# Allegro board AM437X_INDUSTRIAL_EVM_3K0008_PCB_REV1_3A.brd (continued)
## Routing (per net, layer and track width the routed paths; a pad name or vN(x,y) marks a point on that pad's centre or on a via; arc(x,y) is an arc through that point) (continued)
DDR_D30: length 36.7
  TOP w0.102: U11.AC1 87.81,58.53 88.35,58.53 88.9,59.08 91.89,59.08 92.99,57.98 92.99,55.91 94.93,53.97 94.93,52.95 95.05,52.83 95.05,52.62 96.17,51.5 97.74,51.5 98.25,51 98.25,49.47 98.04,49.26 97.31,49.26 97.19,49.14 97.19,48.98 97.31,48.86 98.13,48.86 98.25,48.74 98.25,48.57 98.13,48.45 97.2,48.45 97.08,48.33 97.08,48.16 97.2,48.04 98.13,48.04 98.25,47.92 98.25,46.07 98.13,45.95 97.88,45.95 97.76,45.83 97.76,45.66 97.88,45.54 98.13,45.54 98.25,45.43 98.25,45.26 98.13,45.14 97.88,45.14 97.76,45.02 97.76,44.85 97.88,44.73 98.13,44.73 98.25,44.61 98.25,44.33 97.4,43.49 v1(96.63,43.49) ; U21.B8 94.5,39.84 94.5,39.85 94.36,39.99 94.36,40.8 95.25,41.68 96.28,41.68 96.6,42 v1(96.6,42.24)
  BOTTOM w0.102: v1(96.6,42.24) 96.38,42.47 96.38,43.23 v1(96.63,43.49)
DDR_D31: length 36.8
  TOP w0.102: v1(95.57,53.11) 95.97,53.11 96.3,53.44 96.3,54.23 96.15,54.38 95.28,54.38 95.07,54.6 95.07,54.77 95.45,55.15 95.45,55.32 95.33,55.44 95.17,55.44 94.78,55.05 94.61,55.05 94.49,55.17 94.49,55.34 94.88,55.73 94.88,55.9 94.76,56.02 94.59,56.02 94.2,55.63 94.03,55.63 93.48,56.18 93.48,58.56 92.39,59.66 87.33,59.66 U11.AC2 ; v1(91.74,51) 91.74,50.4 90.55,49.21 90.55,40.59 U21.A3
  BOTTOM w0.102: v1(95.57,53.11) 95.56,53.1 95.56,51.93 95.87,51.61 95.87,51.45 95.76,51.33 95.6,51.33 95.06,51.87 94.9,51.87 94.78,51.76 94.78,51.59 95.32,51.06 95.32,50.9 95.21,50.78 95.04,50.78 94.51,51.32 94.35,51.32 94.03,51 v1(91.74,51)
DDR_DQM0: length 37.7
  TOP w0.102: U11.F4 v1(75.61,61.69) ; U20.E7 75.26,37.46 74.95,37.78 74.8,37.78 74.71,37.68 74.71,37.38 74.57,37.25 74.27,37.25 74.13,37.1 73.96,37.1 73.85,37.21 73.85,37.38 74.37,37.9 74.37,38.02 74.06,38.33 v1(73.63,38.33)
  BOTTOM w0.102: v1(73.63,38.33) 73.15,38.81 73.15,40.61 72.6,41.16 72.6,42.71 71.74,43.57 70.67,43.57 70.16,43.57 69.7,44.03 69.7,45.16 69.04,45.82 69.04,52.83 70.08,53.87 71.9,53.87 73.1,55.07 73.27,55.07 73.39,54.95 73.56,54.95 73.68,55.07 73.68,55.24 73.55,55.36 73.55,55.53 73.67,55.65 73.84,55.65 73.96,55.53 74.13,55.53 74.25,55.65 74.25,55.81 74.13,55.94 74.13,56.11 74.25,56.22 74.42,56.22 74.54,56.1 74.71,56.1 74.83,56.22 74.83,56.39 74.7,56.51 74.7,56.8 74.92,57.02 75.02,57.02 75.14,57.14 75.14,57.3 75.02,57.42 74.92,57.42 74.8,57.54 74.8,57.71 74.92,57.83 75.02,57.83 75.14,57.95 75.14,58.12 75.02,58.24 74.92,58.24 74.8,58.35 74.8,58.52 74.92,58.64 75.02,58.64 75.14,58.76 75.14,58.93 75.02,59.05 74.92,59.05 74.8,59.17 74.8,59.46 75.9,60.55 75.9,61.4 v1(75.61,61.69)
DDR_DQM1: length 31.7
  TOP w0.102: U20.D3 72.24,38.2 72.24,38.53 72.39,38.68 72.39,38.73 73.33,39.68 73.33,41.35 71.06,43.62 v1(71.06,44.8) ; v1(71.06,46.17) 71.06,46.53 71.32,46.78 71.48,46.78 71.66,46.6 71.84,46.6 71.96,46.72 71.96,46.88 71.77,47.07 71.77,47.24 72.86,48.33 72.86,49.79 72.46,50.19 71.58,50.19 71.15,50.62 71.15,51.23 71.61,51.69 71.87,51.69 72.58,52.4 72.58,52.57 72.14,53 72.14,53.17 72.26,53.29 72.43,53.29 72.86,52.85 73.03,52.85 73.15,52.97 73.15,53.14 72.72,53.57 72.72,53.74 72.84,53.86 73.01,53.86 73.44,53.43 73.61,53.43 76.89,56.72 76.89,59.66 U11.H2
  BOTTOM w0.102: v1(71.06,46.17) v1(71.06,44.8)
DDR_DQM2: length 36.9
  TOP w0.102: v1(92.75,37.37) 92.9,37.23 93.28,37.23 93.31,37.26 93.88,37.26 U21.E7 ; U11.V6 83.74,62.6 84.22,63.08 v1(84.54,63.08)
  BOTTOM w0.102: v1(84.54,63.08) 84.54,62.29 84.25,62 84.25,61.37 85.02,60.6 85.02,58.61 84.1,57.68 84.1,56.34 84.31,56.13 85.08,56.13 85.2,56.01 85.2,55.31 85.32,55.19 85.49,55.19 85.61,55.31 85.61,56.01 85.72,56.13 85.94,56.13 86.03,56.04 86.03,55.02 85.91,54.9 85.55,54.9 85.43,54.78 85.43,54.61 85.55,54.49 85.91,54.49 86.03,54.38 86.03,54.11 88.97,51.17 88.97,50.94 90.98,48.93 92.35,48.93 92.8,48.48 92.8,45.72 92.61,45.52 92.61,41.93 92.51,41.83 92.51,38.02 92.75,37.78 v1(92.75,37.37)
DDR_DQM3: length 36.7
  TOP w0.102: v1(89.16,46.88) 89.16,48.2 89.56,48.6 89.56,50.33 89.37,50.52 89.37,50.84 89.58,51.05 89.58,51.57 89.38,51.77 88.86,51.77 88.74,51.65 88.74,51.39 88.63,51.27 88.46,51.27 88.34,51.39 88.34,51.65 88.22,51.77 87.83,51.77 85.37,54.23 85.37,55.7 84.14,56.94 84.14,57.51 85.03,58.41 U11.Y1 ; U21.D3 91.02,38.02 91.17,38.17 91.34,38.17 91.47,38.04 91.47,37.78 91.6,37.65 91.79,37.65 91.93,37.79 91.93,38.33 92.12,38.52 92.29,38.52 92.41,38.4 92.41,38.25 92.52,38.13 93.46,38.13 93.56,38.24 93.56,38.79 93.34,39.01 93.19,39.01 93.11,38.93 93.11,38.52 93.03,38.44 92.86,38.44 92.76,38.54 92.76,38.92 92.68,39.01 92.11,39.01 91.63,38.53 90.93,38.53 90.75,38.36 89.9,38.36 89.56,38.7 89.56,40.62 89.21,40.97 89.21,41.14 89.09,41.26 89.05,41.26 88.93,41.38 88.93,41.54 89.05,41.66 89.09,41.66 89.21,41.78 89.21,41.95 89.09,42.07 89.05,42.07 88.93,42.19 88.93,42.36 89.05,42.48 89.09,42.48 89.21,42.59 89.21,42.76 89.09,42.88 89.05,42.88 88.93,43 88.93,43.17 89.05,43.29 89.09,43.29 89.21,43.41 89.21,43.58 89.09,43.69 89.05,43.69 88.93,43.81 88.93,43.98 89.05,44.1 89.09,44.1 89.21,44.22 v1(89.21,44.85)
  BOTTOM w0.102: v1(89.16,46.88) 89.21,46.83 v1(89.21,44.85)
DDR_DQS0: length 37.8
  TOP w0.102: v1(66.64,51.91) 66.84,51.72 67.71,51.72 68.15,52.15 68.15,52.28 67.73,52.69 67.73,53.06 68,53.33 68.36,53.33 68.78,52.91 68.91,52.91 69,53 69,53.13 68.62,53.5 68.62,53.87 68.89,54.13 70.51,54.13 72.39,56.01 73.39,56.01 75.64,58.25 75.64,59.71 U11.F2 ; U20.F3 72.56,36.42 v1(72.59,36.45)
  BOTTOM w0.102: v1(66.64,51.91) 66.46,51.73 65.98,51.73 65.87,51.62 65.87,50.81 66.8,49.88 66.8,48.95 66.51,48.66 66.27,48.66 66.11,48.49 66.11,48.25 65.94,48.08 65.94,46.16 66.64,45.47 66.64,43.95 68.8,41.78 71.12,41.78 71.28,41.62 71.28,38.64 72.11,37.82 72.11,37.21 72.59,36.73 v1(72.59,36.45)
DDR_DQS1: length 31.7
  TOP w0.102: v1(74.84,39.23) 75.25,38.82 U20.C7 ; U11.J2 77.89,59.77 77.59,59.47 77.59,55.68 73.96,52.04 73.96,51.27 74.25,50.98 75.12,50.98 75.24,50.86 75.24,50.69 75.12,50.57 74.32,50.57 74.02,50.27 74.02,49.77 74.33,49.46 75.21,49.46 75.3,49.37 75.3,49.24 75.21,49.15 74.47,49.15 74.21,48.89 74.21,48.52 74.47,48.26 75.21,48.26 75.3,48.17 75.3,48.04 75.21,47.95 74.45,47.95 74.19,47.69 74.19,47.32 74.45,47.06 75.21,47.06 75.3,46.97 75.3,46.84 75.21,46.76 74.66,46.76 73.27,45.36 73.27,44.55 v1(73.08,44.36)
  BOTTOM w0.102: v1(74.84,39.23) 74.44,39.63 74.44,40.25 74.57,40.37 74.57,42.32 73.28,43.6 73.28,44.16 v1(73.08,44.36)
DDR_DQS2: length 36.9
  TOP w0.102: U11.W1 84.38,59.05 83.88,58.55 83.88,57.93 83.37,57.43 83.37,54.58 87.04,50.91 87.04,50.37 87.7,49.71 88.02,49.71 v1(88.21,49.91) ; U21.F3 90.73,36.21 90.78,36.16 90.96,36.16 91.27,36.46 91.27,36.75 91.41,36.89 v1(92.01,36.89)
  BOTTOM w0.102: v1(92.01,36.89) 91.62,36.89 91.46,37.05 90.95,37.05 90.45,37.55 90.45,37.98 90.68,38.22 90.68,38.34 90.45,38.58 90.45,39.01 89.68,39.78 89.68,41.6 89.77,41.69 90.96,41.69 91.22,41.95 91.22,42.32 90.96,42.59 89.77,42.59 89.68,42.67 89.68,43.3 89.76,43.37 91.16,43.37 91.43,43.65 91.43,44.15 90.8,44.78 90.8,45.35 90.98,45.54 90.98,45.74 90.8,45.92 90.8,47.53 89.86,48.47 89.49,48.47 88.89,47.87 88.77,47.87 88.68,47.96 88.68,48.09 89.27,48.68 89.27,49.06 88.61,49.72 88.4,49.72 v1(88.21,49.91)
DDR_DQS3: length 36.8
  TOP w0.102: v1(93.32,45.26) 93.47,45.41 93.47,45.56 93.75,45.84 93.75,46.34 93.63,46.46 92.47,46.46 92.2,46.74 92.2,47.19 92.47,47.46 94.04,47.46 94.14,47.56 94.14,47.73 94.01,47.86 92.58,47.86 92.29,48.16 92.29,48.57 92.58,48.86 93.63,48.86 93.75,48.98 93.75,49.7 93.33,50.11 93.33,50.52 93.75,50.93 93.75,51.36 93.3,51.81 93.3,51.87 93.3,52.16 92.5,52.96 91.51,52.96 91.22,53.25 91.22,53.54 91.1,53.66 90.94,53.66 90.82,53.54 90.82,53.25 90.52,52.96 90.11,52.96 89.82,53.25 89.82,53.54 89.7,53.66 89.53,53.66 89.41,53.54 89.41,53.25 89.12,52.96 88.26,52.96 87.84,53.38 87.84,53.8 88.02,53.98 88.02,54.15 87.9,54.27 87.73,54.27 87.55,54.08 87.14,54.08 86.79,54.44 86.79,57.56 85.75,58.6 85.75,59.29 U11.AA1 ; U21.C7 93.74,39.01 93.74,39.14 93.56,39.32 93.11,39.32 92.59,39.84 92.59,41.53 93.55,42.49 93.55,42.84 v1(93.29,43.1)
  BOTTOM w0.102: v1(93.29,43.1) 93.29,45.24 v1(93.32,45.26)
DDR_DQSN0: length 37.8
  TOP w0.102: U20.G3 72.31,35.62 v1(72.54,35.84) ; U11.F1 75.94,58.13 73.51,55.71 72.51,55.71 70.64,53.84 69.01,53.84 68.92,53.74 68.92,53.62 69.29,53.25 69.29,52.88 69.03,52.62 68.66,52.62 68.24,53.03 68.12,53.03 68.03,52.94 68.03,52.81 68.44,52.4 68.44,52.03 67.83,51.42 66.82,51.42 v1(66.64,51.25)
  BOTTOM w0.102: v1(66.64,51.25) 66.46,51.43 66.29,51.43 66.17,51.31 66.17,50.93 67.1,50 67.1,48.82 66.23,47.96 66.23,46.29 66.93,45.59 66.93,44.07 68.92,42.08 71.25,42.08 71.58,41.75 71.58,38.77 72.41,37.94 72.41,37.34 73.01,36.73 73.01,36.05 72.81,35.84 v1(72.54,35.84)
DDR_DQSN1: length 31.7
  TOP w0.102: U20.B7 74.86,40.02 v1(74.86,40.08) ; v1(73.78,44.36) 73.56,44.58 73.56,45.24 74.78,46.46 75.33,46.46 75.59,46.72 75.59,46.97 75.59,47.09 75.33,47.35 74.57,47.35 74.48,47.44 74.48,47.57 74.57,47.66 75.33,47.66 75.59,47.92 75.59,48.29 75.33,48.55 74.59,48.55 74.51,48.64 74.51,48.77 74.59,48.86 75.33,48.86 75.59,49.12 75.59,49.49 75.33,49.75 74.46,49.75 74.31,49.89 74.31,50.15 74.44,50.27 75.24,50.27 75.53,50.57 75.53,50.98 75.24,51.27 74.37,51.27 74.25,51.39 74.25,51.92 74.58,52.25 74.75,52.25 74.8,52.19 74.97,52.19 75.09,52.31 75.09,52.48 75.03,52.53 75.03,52.7 75.15,52.82 75.32,52.82 75.38,52.77 75.55,52.77 75.66,52.89 75.66,53.05 75.61,53.11 75.61,53.28 77.89,55.55 U11.J1
  BOTTOM w0.102: v1(73.78,44.36) 73.58,44.15 73.58,43.72 73.67,43.63 73.84,43.63 73.92,43.72 74.09,43.72 74.21,43.6 74.21,43.43 74.13,43.35 74.13,43.18 74.24,43.06 74.41,43.06 74.56,43.21 74.74,43.21 74.86,43.09 74.86,42.92 74.7,42.77 74.7,42.6 74.86,42.44 v1(74.86,40.08)
DDR_DQSN2: length 36.9
  TOP w0.102: v1(88.21,49.25) 88.08,49.38 87.62,49.38 86.74,50.25 86.74,50.79 83.08,54.46 83.08,57.55 83.58,58.06 83.58,58.67 84.09,59.17 84.09,59.71 U11.W2 ; v1(91.7,36.43) 91.63,36.43 91.62,36.41 91.62,36.39 90.84,35.62 U21.G3
  BOTTOM w0.102: v1(88.21,49.25) 88.4,49.43 88.48,49.43 88.98,48.93 88.98,48.81 88.38,48.21 88.38,47.84 88.64,47.58 89.01,47.58 89.61,48.17 89.74,48.17 90.51,47.4 90.51,44.65 91.14,44.02 91.14,43.77 91.04,43.67 89.63,43.67 89.39,43.42 89.39,42.55 89.65,42.29 90.83,42.29 90.92,42.2 90.92,42.08 90.83,41.99 89.65,41.99 89.39,41.72 89.39,39.65 90.15,38.89 90.15,37.43 90.83,36.75 91.34,36.75 91.67,36.43 v1(91.7,36.43)
DDR_DQSN3: length 36.8
  TOP w0.102: U21.B7 93.24,39.62 92.89,39.96 92.89,41.41 93.88,42.41 v1(93.88,43.46) ; v1(93.76,44.54) 93.76,45.44 94.04,45.72 94.04,46.47 93.75,46.76 92.59,46.76 92.49,46.86 92.49,47.03 92.63,47.16 94.17,47.16 94.44,47.44 94.44,47.85 94.13,48.16 92.7,48.16 92.59,48.28 92.59,48.45 92.7,48.57 93.75,48.57 94.04,48.86 94.04,49.82 93.63,50.23 93.63,50.4 94.04,50.81 94.04,51.48 93.59,51.93 93.59,51.99 93.59,52.28 92.62,53.25 91.64,53.25 91.52,53.37 91.52,53.66 91.23,53.95 90.81,53.95 90.52,53.66 90.52,53.37 90.4,53.25 90.23,53.25 90.12,53.37 90.12,53.66 89.82,53.95 89.41,53.95 89.12,53.66 89.12,53.37 89,53.25 88.39,53.25 88.13,53.51 88.13,53.67 88.32,53.86 88.32,54.27 88.02,54.56 87.61,54.56 87.43,54.38 87.26,54.38 87.08,54.56 87.08,57.68 86.04,58.72 86.04,59.64 U11.AA2
  BOTTOM w0.102: v1(93.76,44.54) 93.59,44.36 93.59,43.75 v1(93.88,43.46)
DDR_ODT: length 90.8
  TOP w0.102: U20.K1 70.09,32.84 v1(69.39,32.84) ; v1(88.5,33) 88.71,33.22 U21.K1 ; U11.U1 83.21,59.22 83.21,58.19 82.45,57.43 82.45,54.22 85.62,51.05 85.62,48.61 85.92,48.31 85.92,47.65 v1(85.58,47.31)
  L3_SIG1 w0.102: v1(86.83,36.66) 85.12,38.36 74.23,38.36 73.8,37.93 73.61,37.93 72.19,37.93 71.29,37.03 71.29,35.52 72.11,34.7 72.11,34.24 71.57,33.7 70.65,33.7 69.8,32.84 v1(69.39,32.84)
  L4_SIG2 w0.102: v1(88.5,33) 88.5,33.68 85.65,36.53 81.23,36.53 80.4,35.69 80.4,34.66 79.99,34.25 79.57,34.25 79.02,33.7 78.3,33.7 77.77,33.17 77.29,33.17 77.03,33.43 77.03,33.61 76.48,34.16 74.55,34.16 73.79,34.92 72.08,34.92 71.93,35.08 71.93,36.17 71.78,36.32 71.56,36.32 71.41,36.17 71.41,35.08 71.25,34.92 70.18,34.92 70.03,34.77 70.03,34.3 69.91,34.18 69.72,34.18 69.6,34.06 69.6,33.89 69.72,33.77 69.91,33.77 70.03,33.65 70.03,33.28 69.6,32.84 v1(69.39,32.84) ; v1(85.58,47.31) 86.06,47.31 86.82,46.54 86.82,43.23 85.94,42.35 85.94,41.8 85.82,41.68 85.02,41.68 84.9,41.57 84.9,41.4 85.02,41.28 85.82,41.28 85.94,41.16 85.94,40.99 85.82,40.87 85.02,40.87 84.9,40.75 84.9,40.58 85.02,40.47 85.82,40.47 85.94,40.35 85.94,40.18 85.82,40.06 85.02,40.06 84.9,39.94 84.9,39.77 85.02,39.65 85.82,39.65 85.94,39.53 85.94,38.65 86.83,37.77 v1(86.83,36.66)
  BOTTOM w0.102: v1(88.5,33) 88.21,33 86.74,31.53 86.74,29.97 R517.2
DDR_RASN: length 96.4
  TOP w0.102: v1(79.13,45.75) 79.01,45.75 78.84,45.93 78.84,47.97 78.96,48.09 79.9,48.09 80.02,48.21 80.02,48.38 79.9,48.5 78.96,48.5 78.84,48.62 78.84,49.14 79.17,49.46 79.17,50.18 80.34,51.35 80.34,53.33 80.21,53.46 80.21,56.79 80.93,57.51 80.93,59.14 80.84,59.23 80.84,59.64 U11.N2 ; U21.J3 v1(92.01,34.02) ; v1(72.54,34.29) 72.33,34.29 U20.J3
  L3_SIG1 w0.102: v1(72.54,34.29) 72.62,34.36 72.62,35.05 72.11,35.56 72.11,36.78 72.44,37.11 74.49,37.11 74.59,37.2 75.85,37.2 76.3,36.75 77.77,36.75 78.58,37.57 80.57,37.57 80.69,37.45 80.69,36.85 80.81,36.73 80.98,36.73 81.1,36.85 81.1,37.45 81.22,37.57 81.38,37.57 81.5,37.45 81.5,36.85 81.62,36.73 81.79,36.73 81.91,36.85 81.91,37.45 82.03,37.57 82.2,37.57 82.32,37.45 82.32,36.85 82.44,36.73 82.6,36.73 82.72,36.85 82.72,37.45 82.84,37.57 83.01,37.57 83.13,37.45 83.13,36.85 83.25,36.73 83.42,36.73 83.54,36.85 83.54,37.45 83.65,37.57 83.82,37.57 83.94,37.45 83.94,36.85 84.06,36.73 84.23,36.73 84.35,36.85 84.35,37.45 84.47,37.57 85.24,37.57 86.57,36.24 87.08,36.24 89.38,33.94 91.93,33.94 v1(92.01,34.02)
  L4_SIG2 w0.102: v1(72.54,34.29) 71.82,33.57 70.7,33.57 69.57,32.44 68.74,32.44 68.12,33.05 68.12,34.6 68.58,35.05 68.58,42.06 69.6,43.08 69.75,43.08 69.87,42.96 69.87,42.2 69.99,42.09 70.16,42.09 70.28,42.2 70.28,42.96 70.4,43.08 70.57,43.08 70.68,42.96 70.68,42.2 70.8,42.09 70.97,42.09 71.09,42.2 71.09,42.96 71.21,43.08 71.38,43.08 71.5,42.96 71.5,42.2 71.62,42.09 71.78,42.09 71.9,42.2 71.9,42.96 72.02,43.08 72.19,43.08 72.31,42.96 72.31,42.2 72.43,42.09 72.6,42.09 72.72,42.2 72.72,42.96 72.84,43.08 73,43.08 73.12,42.96 73.12,42.2 73.24,42.09 73.41,42.09 73.53,42.2 73.53,42.96 73.65,43.08 73.82,43.08 73.94,42.96 73.94,42.2 74.05,42.09 74.22,42.09 74.34,42.2 74.34,42.96 74.46,43.08 75.42,43.08 77.32,44.98 77.32,45.72 77.57,45.97 78.91,45.97 v1(79.13,45.75)
  BOTTOM w0.102: v1(92.01,34.02) 92.28,34.29 93.6,34.29 93.93,33.96 95.61,33.96 95.64,33.99 96.72,33.99 97.16,34.42 97.16,34.8 R503.2
DDR_RESETN: length 86.4
  TOP w0.102: 70.71,27.29 70.71,26.83 73.14,24.4 80,24.4 85.49,29.89 ; v1(85.73,45.81) 86.18,45.81 87.15,44.84 87.15,41.65 86.64,41.15
  TOP w0.13: v1(89.93,27.63) 89.92,27.63 89.92,28.4 U21.T2 ; U20.T2 71.16,28.42 v1(70.71,27.96) 70.71,27.29 ; 86.64,41.15 86.11,40.61 86.11,35.74 86.64,35.2 86.64,31.04 85.49,29.89 ; U11.T1 82.43,58.86 v1(82.6,58.7)
  L3_SIG1 w0.102: 83.26,56.13 83.26,55.92 86.56,52.62 86.56,50.73 86.74,50.55 86.74,47.14 85.73,46.13 v1(85.73,45.81)
  L3_SIG1 w0.13: 83.26,56.13 83.26,56.14 83.26,58.03 v1(82.6,58.7)
  L4_SIG2 w0.102: 72.05,27.29 72.05,26.55 73.34,25.27 80.09,25.27 80.41,24.94 82.42,24.94 82.75,25.27 85.49,25.27
  L4_SIG2 w0.13: 85.49,25.27 92.32,25.27 93.12,26.06 93.12,27.38 92.43,28.07 92.43,29.39 92.18,29.64 91.83,29.64 91.56,29.36 91.12,29.36 89.92,28.16 89.92,27.63 v1(89.93,27.63) ; 72.05,27.29 72.05,27.38 71.47,27.96 v1(70.71,27.96)
DDR_WEN: length 97.7
  TOP w0.102: U11.N4 v1(80.96,61.29) ; v1(72.67,33.02) 72.66,33.02 U20.L3 ; U21.L3 91.85,32.42 v1(91.87,32.44)
  L3_SIG1 w0.102: v1(78.31,48.01) 78.31,48.46 78.33,48.48 78.33,48.84 77.8,49.37 77.8,50.8 79.63,52.64 79.63,52.84 81.05,54.26 81.05,55.92 81.27,56.13 81.27,56.85 80.09,58.03 80.09,60.42 v1(80.96,61.29)
  L4_SIG2 w0.102: v1(91.87,32.44) 91.87,33.17 91.62,33.42 90.71,33.42 90.59,33.54 90.59,33.82 90.47,33.93 90.3,33.93 90.18,33.82 90.18,33.54 90.06,33.42 89.56,33.42 88.99,32.85 88.99,32.85 88.7,32.56 88.21,32.56 87.81,32.97 87.81,33.69 86.34,35.16 85.42,35.16 85.3,35.28 85.3,35.82 85.18,35.94 85.01,35.94 84.89,35.82 84.89,35.28 84.77,35.16 84.6,35.16 84.48,35.28 84.48,35.82 84.37,35.94 84.2,35.94 84.08,35.82 84.08,35.28 83.96,35.16 83.79,35.16 83.67,35.28 83.67,35.92 83.55,36.04 83.38,36.04 83.27,35.92 83.27,35.28 83.15,35.16 82.98,35.16 82.86,35.28 82.86,35.95 82.74,36.07 82.57,36.07 82.45,35.95 82.45,35.28 82.33,35.16 82.17,35.16 82.05,35.28 82.05,35.97 81.93,36.09 81.76,36.09 81.64,35.97 81.64,35.28 81.52,35.16 81.24,35.16 80.8,34.73 80.8,34.42 80.23,33.85 79.77,33.85 79.22,33.3 78.3,33.3 77.94,32.94 75.62,32.94 75.14,33.41 74.26,33.41 73.86,33.02 v1(72.67,33.02)
  BOTTOM w0.102: v1(72.67,33.02) 73.46,33.02 74.6,34.16 80.01,34.16 81.16,35.31 81.16,36.26 81,36.43 79.46,36.43 79.35,36.54 79.35,36.81 79.24,36.93 78.93,36.93 78.85,37.01 78.85,37.59 78.97,37.71 79.61,37.71 79.73,37.83 79.73,38 79.61,38.12 78.97,38.12 78.85,38.24 78.85,38.4 78.97,38.52 79.79,38.52 79.91,38.64 79.91,38.81 79.79,38.93 78.97,38.93 78.85,39.05 78.85,39.22 78.97,39.34 79.94,39.34 80.06,39.46 80.06,39.62 79.94,39.74 78.97,39.74 78.85,39.86 78.85,40.03 78.97,40.15 79.94,40.15 80.06,40.27 80.06,40.44 79.94,40.56 78.97,40.56 78.85,40.68 78.85,40.84 78.97,40.96 79.94,40.96 80.06,41.08 80.06,41.25 79.94,41.37 78.97,41.37 78.85,41.49 78.85,41.66 78.97,41.78 79.94,41.78 80.06,41.89 80.06,42.06 79.94,42.18 78.97,42.18 78.85,42.3 78.85,42.47 78.97,42.59 79.94,42.59 80.06,42.71 80.06,42.88 79.94,42.99 78.97,42.99 78.85,43.11 78.85,43.46 78.97,43.58 79.54,43.58 79.67,43.7 79.67,43.87 79.55,43.98 78.97,43.98 78.85,44.1 78.85,44.46 79.91,45.51 79.91,46.02 78.31,47.62 v1(78.31,48.01) ; R529.2 92.94,26.31 92.94,27.61 92.42,28.13 92.42,29.43 91.82,30.02 91.82,30.4 91.6,30.62 91.6,31.12 91.87,31.39 v1(91.87,32.44)
DRAIN0: length 12.6
  TOP w0.13: J1.19 90.17,111.82 D3.1 90.17,110.11 88.47,108.41 88.47,107.24 89.66,106.05 U5.3
DRAIN1: length 19.8
  TOP w0.13: D4.1 92.33,110.19 93.18,111.05 v1(93.24,111.05) 93.56,111.37 93.56,115.79 J1.20 ; v1(88.39,102.36) U5.4
  L3_SIG1 w0.13: v1(93.24,111.05) 90.68,108.48 90.68,104.65 v1(88.39,102.36)
DRAIN2: length 21
  TOP w0.13: D5.1 v1(94.49,111.25) 95.12,111.89 J1.21 ; v1(87.12,102.36) U5.5
  L3_SIG1 w0.13: v1(94.49,111.25) 94.22,111.52 91.93,111.52 89.43,109.02 88.21,109.02 86.42,107.22 86.42,103.06 v1(87.12,102.36)
DRAIN3: length 26.7
  TOP w0.13: J1.22 96.47,115.43 96.47,111.38 v1(96.65,111.2) D6.1 ; v1(85.85,102.23) U5.6
  L3_SIG1 w0.13: v1(85.85,102.23) 85.85,107.09 88.09,109.32 88.85,109.32 91.35,111.83 96.02,111.83 v1(96.65,111.2)
DRAIN4: length 26
  TOP w0.13: U5.11 v1(85.85,101.22) ; J1.23 98.81,113.09 D7.1 v1(97.82,110.15)
  L3_SIG1 w0.13: v1(85.85,101.22) 85.85,100.69 86.43,100.11 86.65,99.9 87.59,99.9 89.3,101.6 91.34,101.6 96.39,106.65 96.39,108.73 v1(97.82,110.15)
DRAIN5: length 29.3
  TOP w0.13: J1.24 98.81,115.63 98.81,113.92 100.97,111.76 D8.1 99.9,109.09 99.9,107.36 98.97,106.43 97.41,106.43 95.85,104.86 95.85,102.83 95,101.98 91.9,101.98 91.31,101.39 88.26,101.39 87.12,100.25 U5.12
DRAIN6: length 27.2
  TOP w0.13: J1.25 103,111.44 D9.1 102.12,109.28 102.12,106.21 98.65,102.74 96.22,102.74 95.12,101.65 92.2,101.65 91.63,101.08 88.76,101.08 88.39,100.71 U5.13
DRAIN7: length 30.5
  TOP w0.13: J1.26 101.47,115.5 101.47,113.66 104.99,110.15 D10.1 104.04,109.16 104.04,107.21 98.15,101.32 92.37,101.32 91.82,100.77 90.04,100.77 89.66,100.39 U5.14
EECS: length 23.7
  TOP w0.13: U16.1 119.51,45.59 119.83,45.27 125.73,45.27 126.11,45.65 126.11,51.47 125.13,52.45 121.49,52.45 120.48,53.46 U13.63
EEDATA: length 20.8
  TOP w0.13: U16.3 119.13,48.13 119.38,48.39 119.95,47.81 125.03,47.81 125.41,48.2 125.41,51.29 124.87,51.83 121.16,51.83 119.48,53.52 U13.61
EESK: length 21.9
  TOP w0.13: U13.62 119.98,53.48 121.31,52.14 125,52.14 125.72,51.42 125.72,47.3 125.25,46.83 123.86,46.83 123.57,46.54 119.7,46.54 119.38,46.86 U16.2
EHRPWM3_SYNCO: length 2.6
  TOP w0.13: R253.1 105.35,8.32 J16.23
EMU2: length 11
  TOP w0.13: TP4.1 138.34,89.75 138.34,85.38 137.54,84.58 J7.17
EMU3: length 5
  TOP w0.13: TP6.1 126.24,84.58 J7.18
EMU4: length 7.3
  TOP w0.13: TP5.1 138.03,88.03 138.03,86.47 137.41,85.85 J7.19
EMU_RSTN: length 4
  TOP w0.13: J7.15 v1(137.67,83.31)
  BOTTOM w0.13: v1(137.67,83.31) R389.1 C174.1
EMU_USB_DM: length 17
  TOP w0.102: v1(130.06,63.23) 130.3,62.99 130.56,62.99 130.81,62.74 130.81,62.13 129.04,60.36 123.7,60.36 123.55,60.21 U13.7
  BOTTOM w0.102: 132.45,63.17 132.26,62.98 130.31,62.98 v1(130.06,63.23) ; 132.45,63.17 U47.5 ; 132.45,63.17 132.64,62.98 133.58,62.98 134.02,63.43 135.18,63.43 135.39,63.64 J18.2
EMU_USB_DP: length 16.4
  TOP w0.102: v1(130.06,62.57) 130.27,62.78 130.47,62.78 130.59,62.65 130.59,62.22 128.95,60.58 127.36,60.58 127.24,60.71 126.83,60.71 126.7,60.58 126.29,60.58 126.17,60.71 125.76,60.71 125.63,60.58 123.7,60.58 123.56,60.71 U13.8
  BOTTOM w0.102: v1(130.06,62.57) 130.26,62.76 131.3,62.76 131.42,62.65 131.45,62.61 ; J18.3 135.42,62.99 135.2,63.21 134.11,63.21 133.67,62.76 131.61,62.76 131.45,62.61 ; 131.45,62.61 U47.3
ENDAT_EN: length 124.1
  L4_SIG2 w0.13: v1(67.18,89.41) 64.06,92.54 61.53,92.54 59.43,90.44 59.43,87.86 59.28,87.72 59.28,86.18 57.82,84.72 57.82,78.04 55.32,75.54 54.58,75.54 53.21,74.17 53.21,70.03 50.46,67.27 45.94,67.27 42.82,64.16 42.44,64.16 40.13,61.85 40.13,60.2 38.79,58.86 38.79,54.56 40.77,52.58 40.77,51.56 38.69,49.48 34.18,49.48 33.72,49.02 30.81,49.02 27.63,45.85 21.84,45.85 19.94,43.94 19.94,33.71 v1(21.08,32.56)
  BOTTOM w0.13: v1(67.18,89.41) 68.66,87.93 70.56,87.93 73.28,85.22 73.28,83.95 ; v1(21.08,32.56) 22.73,30.91 22.73,29.57 21.4,28.24 19.12,28.24 18.19,27.3 14.92,27.3 14.1,28.13 R519.1 U57.2
EQEP1_INDEX: length 3.4
  TOP w0.13: R241.1 77.34,5.85 J16.51
EQEP1_STROBE: length 76.4
  L4_SIG2 w0.13: v1(63.55,55.24) 62.84,54.53 62.84,53.8 59.12,50.08 59.12,40.56 60.13,39.55 60.13,35.6 65.3,30.44 65.3,28.64 66.85,27.09 66.85,26.33 70.52,22.65 70.52,21.39 75.83,16.09 76.47,16.09 76.91,15.65 76.91,11.76 74.04,8.89 74.04,8.38 74.73,7.7 75.77,7.7 76.07,7.39 76.07,6.57 J16.53
  BOTTOM w0.13: R465.1 59.94,61.09 58.93,60.07 58.93,58.67 59.68,57.92 59.68,56.9 61.33,55.24 v1(63.55,55.24)
EQEP1A_IN: length 65.1
  TOP w0.13: v1(71.37,8.15) 71.37,5.87 J16.57
  L4_SIG2 w0.13: v1(71.37,8.15) 71.96,8.74 71.96,10.36 73.3,11.7 73.3,14.54 71.8,16.03 71.8,16.04 69.77,18.07 69.73,18.07 64.12,23.69 62.84,23.69 55.07,31.46 55.07,40.98 56.34,42.25 56.34,51.23 60.85,55.75 v1(60.85,56.39)
  BOTTOM w0.13: 60.58,59.31 60.58,58.74 60.58,58.74 60.58,56.67 v1(60.85,56.39)
EQEP1B_IN: length 65.9
  TOP w0.13: v1(74.68,8.64) 73.35,7.31 J16.55
  L4_SIG2 w0.13: v1(64.23,55.63) 64.23,54.95 63.27,54 63.27,53.54 59.43,49.7 59.43,40.69 60.44,39.68 60.44,36.03 65.61,30.87 65.61,28.77 67.16,27.21 67.16,26.45 70.83,22.78 70.83,21.52 75.95,16.41 75.97,16.41 75.98,16.4 76.6,16.4 77.34,15.66 77.34,11.3 v1(74.68,8.64)
  BOTTOM w0.13: R471.1 63.63,57.66 62.92,56.95 62.61,56.95 62.33,56.67 62.33,56.03 62.66,55.7 64.15,55.7 v1(64.23,55.63)
EQEP2_INDEX: length 98.9
  TOP w0.13: v1(66.42,65.91) 66.42,65.83 66.73,65.52 73.01,65.52 U11.B11
  L4_SIG2 w0.13: v1(66.42,65.91) 67.36,64.97 67.36,63.68 66.49,62.81 64.97,62.81 64.63,62.47 64.63,61.73 63.34,60.44 63.34,57.4 61.65,55.72 61.65,54.46 57.72,50.54 57.72,36.01 57.05,35.34 57.05,33.78 58.83,32 59.29,32 60.26,31.03 60.26,30.12 60.6,29.78 61.06,29.78 62.57,28.26 62.57,26.2 63.5,25.27 64.98,25.27 73.84,16.41 74.5,15.75 74.5,10.87 72.9,9.27 72.9,7.68 74.33,6.25 74.33,3.48 75.11,2.69 86.2,2.69 J16.42
EQEP2_STROBE: length 92.8
  TOP w0.13: U11.A11 67.18,65.85 v1(67.08,65.95)
  L4_SIG2 w0.13: v1(67.08,65.95) 67.69,65.33 67.69,63.2 64.32,59.82 64.32,57.15 62.52,55.36 62.52,53.96 58.81,50.25 58.81,40.44 59.5,39.75 59.5,35.61 60.96,34.16 60.96,32.66 62.69,30.92 63.64,30.92 63.77,31.05 64.25,31.05 64.58,30.72 64.58,28.92 66.54,26.97 66.54,26.08 66.73,25.89 69.44,23.17 69.44,22.04 75.27,16.21 75.53,15.95 75.53,11.01 73.28,8.76 73.28,7.98 74.04,7.21 v2(75.54,7.21)
  BOTTOM w0.13: J16.44 84.37,2.86 76.94,2.86 76.37,3.44 76.37,6.38 v2(75.54,7.21)
EQEP2A_IN: length 89.4
  TOP w0.13: U11.E11 v1(75.29,66.32)
  L4_SIG2 w0.13: J16.46 82.37,4.82 82.37,9.63 86.76,14.02 89.28,14.02 93.34,18.09 93.34,18.11 93.4,18.16 93.4,21.77 97.41,25.79 97.41,32.22 96.89,32.74 96.89,34.73 96.52,35.1 95.75,35.1 93.76,37.09 93.76,37.09 93.41,37.44 93.41,37.77 92.5,38.68 90.81,38.68 89.87,39.63 89.87,40.33 90.51,40.97 90.51,46.96 90.17,47.3 90.06,47.42 89.58,47.89 88.35,47.89 87.43,48.81 87.43,53.21 86.39,54.25 86.39,57.63 85.86,58.15 85.86,59.84 84.37,61.33 84.37,62.3 85.78,63.7 85.78,64.35 85.44,64.69 82.71,64.69 82.34,64.32 77.82,64.32 76.6,65.53 76.07,65.53 v1(75.29,66.32)
EQEP2B_IN: length 88.5
  TOP w0.13: U11.C11 v1(73.98,66.32)
  L4_SIG2 w0.13: v1(73.98,66.32) 75,65.3 76.51,65.3 77.72,64.09 82.51,64.09 82.77,64.35 83.34,64.35 83.86,63.82 83.86,61.14 83.73,61.01 83.73,59.94 84.26,59.41 84.26,56.77 85.56,55.46 85.56,54.47 87.09,52.94 87.09,48.16 87.79,47.45 87.79,46.03 88.11,45.71 89.58,45.71 90.2,45.08 90.2,41.23 89.54,40.57 89.54,39.61 90.85,38.3 92.56,38.3 93.18,37.67 93.18,37.35 93.53,37 93.53,36.99 95.52,35 95.52,34.55 96.63,33.45 96.63,32.62 97.18,32.07 97.18,30.62 96.84,30.28 96.84,29.91 96.84,29.91 96.87,29.87 96.89,29.82 96.9,29.77 96.9,25.91 93.09,22.1 93.09,18.29 89.15,14.35 86.65,14.35 80.37,8.07 80.37,4.82 J16.48
ETH1_LDO_O: length 27.4
  L4_SIG2 w0.508: v1(35.31,79.12) 34.42,80.01 34.42,81.53 30.99,84.96 30.99,86.11 33.4,88.52 33.4,92.33 34.67,93.6 v1(35.56,93.6)
  BOTTOM w0.254: U37.43 38.73,92.96 38.35,92.58 36.58,92.58 v1(35.56,93.6)
  BOTTOM w0.508: Q9.G 36.31,77.23 35.31,78.23 v1(35.31,79.12)
ETH1_MDC: length 4.7
  BOTTOM w0.13: R374.1 37.34,86.61 39.96,89.24 U37.36
ETH1_MDIO: length 2.7
  BOTTOM w0.13: R357.1 39.03,89.96 U37.37
ETH1_RESETN: length 26.9
  BOTTOM w0.13: U37.42 38.74,92.46 38.48,92.2 36.45,92.2 35.56,91.31 35.56,90.55 35.24,90.23 34.09,90.23 33.4,89.53 D20.2 33,89.81 C161.1 30.1,87.76 R361.1 30.99,86.74 30.35,86.1 30.35,84.85 31.95,83.25 31.95,81.95 31.68,81.69 31.68,81.09 32.38,80.39 32.38,78.99 32,78.61 31.37,78.61 31,78.98 U42.4
ETH1_RXCLK: length 8
  BOTTOM w0.13: R400.2 37.97,84.07 37.97,85.6 R373.1 R372.2 39.62,87.38 40.93,88.68 U37.35
ETH1_RXD0: length 7.6
  BOTTOM w0.13: R397.2 R396.2 41.4,83.95 41.4,85.6 R370.1 42.43,86.63 U37.32
ETH1_RXD1: length 7.9
  BOTTOM w0.13: R395.2 42.55,83.95 42.55,85.6 R369.2 R368.1 44.2,86.75 42.93,88.01 U37.31
ETH1_RXD2: length 7.8
  BOTTOM w0.13: R394.2 R393.2 44.7,84.07 44.7,85.47 R367.1 45.34,86.87 44.43,87.78 U37.28
ETH1_RXD3: length 8.9
  BOTTOM w0.13: R392.2 45.97,83.95 45.97,85.6 R366.2 R365.1 46.86,86.87 46.1,86.87 44.93,88.04 U37.27
ETH1_RXDV: length 7.9
  BOTTOM w0.13: U37.33 41.93,87.27 R371.1 40.26,85.6 40.26,84.07 R398.2 R399.2
ETH1_TXCLK: length 41.4
  L3_SIG1 w0.13: v1(56.69,70.13) 56.74,70.18 56.79,70.18 57.15,70.54 57.15,71.19 57.99,72.03 58.68,72.03 60.58,73.93 60.58,85.04 59.13,86.49 54.17,86.49 53.95,86.26 53.06,86.26 52.54,86.78 52.54,86.94 52.24,87.25 51.8,87.25 51.65,87.1 49.71,87.1 48.59,88.21 48.59,88.74 47.75,89.59 v1(47.75,89.96)
  BOTTOM w0.13: R442.1 62.8,69.85 62.23,69.28 58.07,69.28 57.22,70.13 v1(56.69,70.13) ; U37.24 v1(47.75,89.96)
ETH1_TXD0: length 45.5
  TOP w0.13: R102.1 v1(62.86,72.23)
  L3_SIG1 w0.13: v1(62.86,72.23) 64.19,72.23 64.73,72.78 64.73,74.2 64.89,74.35 65.84,74.35 66,74.5 66,74.72 65.84,74.87 64.89,74.87 64.73,75.02 64.73,75.24 64.89,75.39 65.84,75.39 66,75.54 66,75.76 65.84,75.91 64.89,75.91 64.73,76.07 64.73,76.28 64.89,76.43 65.84,76.43 66,76.59 66,76.8 65.84,76.96 64.89,76.96 64.73,77.11 64.73,77.32 64.89,77.48 65.84,77.48 66,77.63 66,77.85 65.84,78 64.89,78 64.73,78.15 64.73,80.24 64.78,80.29 64.78,80.81 64.73,80.85 64.73,82.33 63.69,83.38 63.69,85.64 61.94,87.39 61.11,87.39 59.52,88.98 54.53,88.98 53.59,89.92 53.59,90.96 52.24,92.31 50.96,92.31 50.68,92.6 49.87,92.6 49.73,92.46 v1(48.64,92.46)
  BOTTOM w0.13: v1(48.64,92.46) 47.88,92.46 47.73,92.3 47.42,92.3 47.26,92.46 U37.19
ETH1_TXD1: length 43.7
  TOP w0.13: v1(59.05,69.85) 59.66,70.45 R107.1
  L3_SIG1 w0.13: v1(47.71,91.88) 47.81,91.88 47.85,91.93 49.15,91.93 49.64,91.44 50.55,91.44 50.94,91.84 51.65,91.84 53.06,90.42 53.06,89.28 53.82,88.52 59.33,88.52 61.18,86.67 61.51,86.34 62.1,86.34 62.36,86.09 63.2,85.24 63.2,82.72 63.35,82.57 63.88,82.57 64.03,82.42 64.03,82.2 63.88,82.05 63.35,82.05 63.2,81.9 63.2,81.68 63.35,81.53 63.75,81.53 63.91,81.38 63.91,81.16 63.75,81.01 63.35,81.01 63.2,80.85 63.2,80.52 64.08,79.64 64.08,78.69 64.3,78.47 64.3,74.55 62.39,72.64 62.39,71.8 60.99,70.41 60.63,70.41 59.61,70.41 v1(59.05,69.85)
  BOTTOM w0.13: v1(47.71,91.88) 47.62,91.88 47.54,91.96 U37.20
ETH1_TXD2: length 45.2
  TOP w0.13: v1(58.67,68.67) 60.36,68.67 60.96,68.07 62.89,68.07 63.49,68.67 R123.1
  L3_SIG1 w0.13: v1(58.67,68.67) 58.24,69.11 58.24,69.57 58.5,69.82 58.5,70.51 58.83,70.84 60.81,70.84 61.96,71.98 61.96,72.82 63.65,74.51 63.65,78.4 63.49,78.55 63.27,78.55 63.12,78.7 63.12,78.92 63.27,79.07 63.49,79.07 63.65,79.23 63.65,79.46 62.76,80.34 62.76,85.06 61.92,85.91 61.69,85.91 61.33,85.91 61.32,85.91 60.69,86.54 60.69,86.54 59.17,88.06 53.57,88.06 50.7,90.93 49.17,90.93 v1(48.64,91.46)
  BOTTOM w0.13: U37.21 v1(48.64,91.46)
ETH1_TXD3: length 42.4
  L3_SIG1 w0.13: v1(47.75,90.96) 47.9,90.96 48.51,90.35 48.85,90.35 48.86,90.35 48.87,90.35 50.66,90.35 53.39,87.63 53.44,87.63 53.47,87.6 59.02,87.6 60.26,86.36 60.26,86.36 61.15,85.47 61.74,85.47 62.28,84.93 62.28,80.2 62.61,79.87 62.61,77.94 62.09,77.42 62.09,77.06 62.24,76.9 62.46,76.9 62.61,76.75 62.61,76.54 62.46,76.38 62.24,76.38 62.09,76.23 62.09,75.54 62.23,75.4 62.23,75.06 62.38,74.91 62.71,74.91 62.86,74.76 62.86,74.54 62.71,74.39 62.38,74.39 62.23,74.24 62.23,73.71 61.52,73 61.52,72.16 60.63,71.28 58.45,71.28 v1(58.29,71.12)
  BOTTOM w0.13: U37.22 v1(47.75,90.96) ; R439.1 63.43,70.92 59.08,70.92 58.88,71.12 v1(58.29,71.12)
ETH1_TXEN: length 43.9
  TOP w0.13: R121.1 v1(56.24,69.31)
  L3_SIG1 w0.13: v1(46.99,87.88) 48.77,86.11 50.18,86.11 51.02,85.27 54.3,85.27 54.85,85.82 58.84,85.82 59.82,84.84 59.82,80.62 59.72,80.52 59.72,80.45 59.67,80.4 59.67,78.33 59.08,77.75 59.08,76.74 59.52,76.3 59.52,74.74 59.44,74.66 59.44,74.34 58.64,73.54 58.64,73.08 58.36,72.81 57.94,72.81 57.59,73.15 56.62,73.15 56.27,72.81 54.01,72.81 53.72,72.52 53.72,71.88 53.98,71.63 54.99,71.63 55.37,71.25 55.37,70.15 56.22,69.31 v1(56.24,69.31)
  BOTTOM w0.13: U37.25 45.93,88.94 v1(46.99,87.88)
ETH1GB_25MHZCLK: length 25.2
  TOP w0.13: v1(33.66,98.68) 21.97,98.68 20.95,99.69 18.54,99.69 v1(18.03,99.19)
  BOTTOM w0.13: v1(33.66,98.68) 34.54,98.68 37.21,96.01 37.21,95.38 38.13,94.46 U37.46 ; R323.2 v1(18.03,99.19)
ETH_MDIO_CLK: length 43.8
  TOP w0.13: v1(59.05,74.94) 60.41,74.94 61.08,74.27 64.03,74.27 64.36,73.94 65.6,73.94 69.46,70.08 69.47,70.08 73.01,70.08 U11.B17
  L3_SIG1 w0.13: v1(37.34,84.33) 38.48,83.19 38.48,81.41 41.65,78.24 50.76,78.24 53.41,75.6 56.31,75.6 56.97,74.94 v1(59.05,74.94)
  BOTTOM w0.13: v1(37.34,84.33) R374.2
ETH_MDIO_DATA: length 49.5
  TOP w0.13: v1(38.48,78.49) 37.97,78.99 37.97,82.03 36.58,83.43 v1(36.58,87.76) R66.1 ; v1(56.57,74.68) 56.66,74.77 58.46,74.77 58.83,74.4 60.52,74.4 60.95,73.96 63.81,73.96 64.14,73.64 65.55,73.64 69.44,69.75 U11.A17
  L3_SIG1 w0.13: v1(56.57,74.68) 56.06,75.18 48.57,75.18 46.04,77.71 39.25,77.71 v1(38.48,78.49)
  BOTTOM w0.13: R66.1 v1(36.58,87.76)
ETHER1_D0N: length 17.4
  BOTTOM w0.102: U37.3 41.43,96.54 41.33,96.65 41.33,97.1 40.89,97.54 40.89,98.04 39.27,99.67 39.27,99.67 39.18,99.76 36.11,99.76 33.13,102.73 33.13,104.97 32.4,105.7 31.44,105.7 J4.10
ETHER1_D0P: length 17.2
  BOTTOM w0.102: U37.2 40.93,96.54 41.03,96.65 41.03,96.98 40.6,97.41 40.6,97.92 39.06,99.46 38.21,99.46 38.09,99.34 37.68,99.34 37.56,99.46 35.99,99.46 32.84,102.61 32.84,104.84 32.27,105.41 31.37,105.41 31.27,105.31 31.23,105.17 J4.9
ETHER1_D1N: length 17.1
  BOTTOM w0.102: U37.6 42.93,96.54 42.83,96.65 42.83,97.06 42.6,97.29 42.6,99.14 40.39,101.35 37.06,101.35 35.67,102.73 35.67,104.97 34.94,105.7 33.98,105.7 J4.8
ETHER1_D1P: length 16.9
  BOTTOM w0.102: J4.7 33.77,105.17 33.81,105.31 33.91,105.41 34.81,105.41 35.38,104.84 35.38,102.61 36.94,101.05 40.26,101.05 40.93,100.39 40.93,100.17 41.14,99.95 41.36,99.95 42.3,99.01 42.3,97.17 42.53,96.94 42.53,96.65 42.43,96.54 U37.5
ETHER1_D2N: length 16.2
  BOTTOM w0.102: U37.8 43.93,96.54 43.83,96.65 43.83,97.06 43.59,97.3 43.59,101.07 41.78,102.87 38.99,102.87 38.23,103.63 38.21,103.63 38.21,104.97 37.48,105.7 36.52,105.7 J4.6
ETHER1_D2P: length 16
  BOTTOM w0.102: U37.7 43.43,96.54 43.53,96.65 43.53,96.94 43.29,97.18 43.29,100.94 42.58,101.66 42.36,101.66 42.15,101.87 42.15,102.09 41.66,102.58 38.87,102.58 38.1,103.34 38.09,103.34 37.92,103.51 37.92,104.84 37.35,105.41 36.45,105.41 36.35,105.31 36.31,105.17 J4.5
ETHER1_D3N: length 16.9
  BOTTOM w0.102: J4.4 39.06,105.7 44.16,105.7 45.77,104.09 45.77,97.37 45.33,96.93 45.33,96.6 45.43,96.49 U37.11
ETHER1_D3P: length 16.7
  BOTTOM w0.102: J4.3 38.85,105.17 38.89,105.31 38.99,105.41 44.03,105.41 45.48,103.97 45.48,103.59 45.34,103.45 45.34,103.15 45.48,103.01 45.48,97.49 45.03,97.05 45.03,96.59 44.93,96.49 U37.10
F_ADBUS0: length 3.8
  TOP w0.13: R133.2 125.12,65.91 123.92,64.71 U13.16
F_ADBUS1: length 3.1
  TOP w0.13: R120.2 120.98,67.51 U13.17
F_ADBUS2: length 2.9
  TOP w0.13: U13.18 120.48,67.64 121.54,68.71 R119.2
F_ADBUS3: length 2.7
  TOP w0.13: R118.2 120.53,68.37 119.98,67.82 U13.19
F_ADBUS4: length 2.6
  TOP w0.13: R117.2 118.5,68.3 118.98,67.82 U13.21
F_ADBUS5: length 2.4
  TOP w0.13: R115.2 116.48,69.08 U13.26
F_ADBUS6: length 2.6
  TOP w0.13: U13.23 117.98,68.59 R116.2
F_ADBUS7: length 2.4
  TOP w0.13: R113.2 114.48,69.05 U13.30
FT_SRESET: length 36.9
  TOP w0.13: v1(127.13,51.69) 127.13,52.43 125.2,54.36 R160.2 ; v1(116.46,71.04) R115.1
  L4_SIG2 w0.13: v1(127.13,51.69) 127.13,60.25 125.05,62.32 125.05,63.31 125.5,63.76 125.5,64.72 124.52,65.7 124.52,67.21 121.3,70.43 117.07,70.43 v1(116.46,71.04)
  BOTTOM w0.13: v1(127.13,51.69) 126.26,51.69 126.26,51.69 123.6,51.69 123.17,51.26 U50.1
FT_SRESETB: length 1.6
  BOTTOM w0.13: U51.4 127.65,46.12 R489.2
FT_SRESETN: length 7.7
  BOTTOM w0.13: U50.4 124.47,47.1 124.7,46.87 125.34,46.87 125.6,47.13 125.6,50.3 125.97,50.68 126.74,50.68 127,50.41 U51.2
FT_VBUS: length 9
  TOP w0.508: v3(123.82,51.05) 121.67,51.05 121.16,50.55 117.86,50.55 117.23,51.18 R170.1
  BOTTOM w0.381: U50.2 v3(123.82,51.05)
FTDI_REF: length 4
  TOP w0.13: U13.6 121.93,59.71 v1(121.67,59.98)
  BOTTOM w0.13: R460.1 122.55,60.86 v1(121.67,59.98)
FTDI_VPHY: length 2.3
  TOP w0.254: v3(121.58,58.71) U13.4
  TOP w0.508: v3(120.78,59.18) 121.25,58.71 v3(121.58,58.71)
FTDI_VPLL: length 2.2
  TOP w0.254: U13.9 121.79,61.21 v3(121.54,60.96)
  TOP w0.508: v3(120.78,60.96) v3(121.54,60.96)
GP_I2C_SCL: length 202.1
  TOP w0.13: v1(83.16,100.61) 81.89,100.61 81.28,101.22 81.28,104.52 83.21,106.45 83.21,111.61 82.73,112.09 68.51,112.09 67.18,113.41 67.18,115.32 65.97,116.53 60.71,116.53 59.58,115.41 58.35,115.41 58.34,115.4 54.68,115.4 53.85,116.22 49.99,116.22 46.76,112.99 46.76,106.22 47.5,105.49 47.5,104.01 45.2,101.72 34.28,101.72 33.78,101.22 33.78,101.22 33.15,100.58 27.89,100.58 27.12,101.35 R22.2
  L4_SIG2 w0.13: v1(99.39,79.71) 99.07,80.03 99.07,87.12 95.7,90.49 95.56,90.63 95.56,91.39 87.86,99.09 84.68,99.09 v1(83.16,100.61) 83.96,101.41 83.96,102.12 85.19,103.35 88.9,103.35 90.58,105.03 95.81,105.03 99.12,108.34 101.61,108.34 106.84,113.57 106.84,117.38 107.57,118.11 121.67,118.11 128.14,111.63 133.22,111.63 137.03,107.82 v1(137.03,103)
  BOTTOM w0.13: v1(83.16,100.61) 83.22,100.61 84.33,101.72 84.33,102.11 84.58,102.36 U32.6 ; v1(99.39,79.71) 98.81,79.12 98.81,77.91 99.11,77.6 R425.1 ; U31.8 135.02,103.36 135.38,103 v1(137.03,103)
GP_I2C_SDA: length 207.7
  TOP w0.13: v1(83.03,101.48) 82.52,101.48 81.59,102.41 81.59,104.32 83.81,106.54 85.59,106.54 86.11,107.06 86.11,110.23 83.94,112.39 68.63,112.39 67.49,113.54 67.49,115.44 66.1,116.84 60.58,116.84 59.46,115.71 58.22,115.71 58.21,115.7 54.81,115.7 53.98,116.53 48.67,116.53 45.97,113.83 45.97,108.89 45.71,108.63 45.71,108.01 45.71,106.82 47.12,105.41 47.12,104.07 45.08,102.03 34.15,102.03 33.15,101.03 27.88,101.03 26.54,102.36 R21.2
  L4_SIG2 w0.13: v1(137.5,102.36) 137.5,108.24 133.6,112.14 128.65,112.14 122.3,118.49 107.51,118.49 106.54,117.51 106.54,113.77 101.41,108.65 97.68,108.65 96.23,107.19 92.3,107.19 88.77,103.66 84.74,103.66 83.06,101.98 83.06,101.51 v1(83.03,101.48) 82.69,101.13 82.69,100.04 84.28,98.45 87.99,98.45 95.25,91.19 95.25,90.51 98.58,87.18 v1(98.58,80.14)
  BOTTOM w0.13: v1(98.58,80.14) 99.01,80.57 99.54,80.57 99.95,80.16 99.95,78.99 R419.1 ; U31.1 135.02,102 135.38,102.36 v1(137.5,102.36) ; U32.5 83.31,101.76 v1(83.03,101.48)
HDQ: length 5.9
  TOP w0.13: R243.2 80.37,9.25 80.37,4.86 J16.50
IDC_SENSE: length 180
  TOP w0.13: 49.28,28.83 v1(49.28,27.56) ; 105.28,69.98 106.25,70.94 v1(106.3,70.94)
  L3_SIG1 w0.13: v1(112.65,16.76) 109.7,13.82 109.7,8.82 110.37,8.15 110.37,3.3 108.71,1.64 68.28,1.64 v1(66.4,3.53)
  L4_SIG2 w0.13: v1(66.4,3.53) 66.4,6.73 68.2,8.54 69.49,8.54 70.52,9.56 70.52,14.93 64.25,21.2 62.73,21.2 61.25,22.69 59.02,22.69 58.02,23.68 58.02,25.9 57.55,26.37 50.97,26.37 49.78,27.56 v1(49.28,27.56) ; v1(106.3,70.94) 107.95,70.94 108.1,70.79 111.22,70.79 112.35,69.67 114.33,69.67 120.6,63.4 120.6,61.95 119.58,60.93 119.58,59.57 122.63,56.53 122.63,45.59 121.33,44.29 121.33,41.15 122.33,40.16 122.33,35.31 121.85,34.84 121.85,33.74 122.89,32.71 122.89,28.98 121.46,27.55 119.31,27.55 115.87,24.11 115.87,18.85 113.78,16.76 v1(112.65,16.76)
  BOTTOM w0.13: R518.2 C325.1 v1(49.28,27.56)
IND_I2C_SCL: length 102.2
  L4_SIG2 w0.13: v1(113.92,16.26) 116.21,18.55 116.21,24.02 119.44,27.25 121.69,27.25 124.53,30.08 124.53,38.75 122.74,40.53 122.74,42.49 122.93,42.68 122.93,47.29 123.24,47.6 123.24,58.78 122.37,59.65 122.37,63.89 118.79,67.47 116.97,67.47 114.15,70.29 112.16,70.29 111.35,71.1 108.35,71.1 107.49,71.96 105.61,71.96 103.29,74.29 v1(103.29,74.89)
  BOTTOM w0.13: v1(103.29,74.89) 103.28,74.89 102.91,75.26 101.74,75.26 101.44,75.56 R430.1 ; J16.27 105.14,9.63 105.14,14.55 106.59,16 111.12,16 112.14,14.99 112.78,14.99 113.92,16.13 v1(113.92,16.26)
IND_I2C_SDA: length 106.8
  L4_SIG2 w0.13: v1(112.65,15.62) 114.01,15.62 116.52,18.14 116.52,23.89 119.57,26.94 121.82,26.94 125.02,30.14 125.02,38.94 124.12,39.84 123.05,40.9 123.05,42.36 123.24,42.55 123.24,47.16 125.41,49.34 125.41,57.04 122.68,59.78 122.68,64.02 117.75,68.95 115.93,68.95 113.44,71.44 112.16,71.44 112.13,71.41 108.68,71.41 107.79,72.3 105.73,72.3 104.9,73.13 104.9,73.76 v1(103.99,74.68)
  BOTTOM w0.13: v1(112.65,15.62) 111.76,16.51 106.67,16.51 104.83,14.67 104.83,9.76 101.89,6.82 100.33,6.82 J16.29 ; R432.1 101.11,74.95 102.56,74.95 103.09,74.42 103.73,74.42 v1(103.99,74.68)
INDUS_INPUT0: length 4
  BOTTOM w0.13: R295.1 J1.1
INDUS_INPUT1: length 4
  BOTTOM w0.13: R294.1 J1.3
INDUS_INPUT2: length 4
  BOTTOM w0.13: R293.1 J1.5
INDUS_INPUT3: length 4
  BOTTOM w0.13: R292.1 J1.7
INDUS_INPUT4: length 4
  BOTTOM w0.13: R291.1 J1.9
INDUS_INPUT5: length 4
  BOTTOM w0.13: J1.11 R290.1
INDUS_INPUT6: length 4
  BOTTOM w0.13: J1.13 R289.1
INDUS_INPUT7: length 4
  BOTTOM w0.13: R288.1 J1.15
INDUS_INPUTCLK: length 55.4
  TOP w0.13: U4.25 v1(73.29,107.06)
  L4_SIG2 w0.13: v1(55.1,76.07) 57.28,78.26 57.28,85.02 58.75,86.48 58.75,87.94 58.89,88.09 58.89,90.85 61.59,93.56 61.59,94.36 63.41,96.18 65.43,96.18 66.03,96.77 66.03,97.35 68.75,100.07 69.22,100.07 71.13,101.98 71.13,104.15 72.01,105.03 72.01,106.81 72.26,107.06 v1(73.29,107.06)
  BOTTOM w0.13: R437.1 62.72,71.36 59.29,71.36 58.82,71.83 56.95,71.83 55.1,73.68 v1(55.1,76.07)
INDUS_INPUTCSN: length 41.8
  TOP w0.13: R99.1 60.93,72.86 v1(60.32,72.26) ; U4.24 v1(73.94,105.64)
  L4_SIG2 w0.13: v1(60.32,72.26) 60.49,72.26 62.16,73.93 62.64,73.93 64.14,75.44 64.14,79.84 63.79,80.2 63.79,81.8 66.79,84.81 66.79,87.85 68.54,89.6 68.54,91.9 71.31,94.66 71.31,97.14 73.6,99.43 73.6,105.3 v1(73.94,105.64)
INDUS_INPUTLDN: length 51.4
  TOP w0.13: U4.26 v1(72.64,106.55) ; R105.1 62.19,70.96 62.16,70.99 58.86,70.99 v1(57.98,70.1)
  L4_SIG2 w0.13: v1(72.64,106.55) 72.64,103.43 72.4,103.19 72.4,100.23 69.28,97.11 69.28,94.2 68.24,93.16 68.24,89.77 66.49,88.03 66.49,84.93 63.48,81.92 63.48,80.07 63.83,79.72 63.83,76.58 63.83,76.58 63.83,75.57 62.51,74.24 62.03,74.24 60.52,72.73 60.13,72.73 59.85,72.46 59.85,72.01 57.98,70.14 v1(57.98,70.1)
INDUS_INPUTSO: length 17.8
  TOP w0.13: v1(75.23,106.5) 75.23,106.48 74.59,105.83 U4.23
  L4_SIG2 w0.13: v1(74.55,95.76) 74.55,99.2 74.92,99.57 74.92,106.19 v1(75.23,106.5)
  BOTTOM w0.13: U36.2 75.95,92.96 76.2,93.22 76.2,94.11 v1(74.55,95.76)
IS_IHB1: length 164.1
  TOP w0.254: v1(67.95,23.95) 67.95,23.11 75.44,15.62 v1(76.28,15.62) ; v1(85.47,65.79) 85.47,66.06 U11.Y12
  L3_SIG1 w0.254: v1(118.14,35.61) 116.99,35.61 115.27,33.88 113.5,33.88 107.93,28.32 107.93,23.71 106.34,22.11 106.34,20.19 102.26,16.11 102.26,13.51 100.16,11.4 99.53,11.4 98.73,10.6 95.74,10.6 95.09,9.95 92.07,9.95 91.41,10.62 88.69,10.62 88.1,11.2 83.29,11.2 82.47,12.01 78.59,12.01 77.37,13.23 77.37,14.53 v1(76.28,15.62) ; v1(85.47,65.79) 85.47,65.66 88.01,63.12 103.56,63.12 105.87,65.43 105.87,69.55 v1(106.05,69.72)
  L4_SIG2 w0.254: v1(118.14,35.61) 118.2,35.68 118.2,44.99 119.07,45.85 119.07,58.16 118.09,59.15 118.09,61.45 116.97,62.57 116.97,65.11 114.41,67.67 112.01,67.67 111.75,67.92 109.98,67.92 108.18,69.72 v1(106.05,69.72)
  BOTTOM w0.254: R509.2 C309.1 ; R509.2 62.99,34.42 R501.1 ; R509.2 62.8,33.08 62.65,33.08 61.72,32.16 61.72,29.46 62.2,28.98 64.79,28.98 65.46,28.31 65.46,25.6 67.11,23.95 v1(67.95,23.95) ; 107.06,70.36 106.58,70.36 106.05,69.82 v1(106.05,69.72)
IS_IHB2: length 316.1
  TOP w0.13: v1(85.35,67.5) 85.68,67.16 U11.AA13
  TOP w0.254: v1(102.36,56.26) 102.36,57.53 103.78,58.95 108.43,58.95 109.22,59.74 109.22,61.04 108.2,62.05 108.2,66.5 108.61,66.9 108.61,71.78 v2(108.84,72.01) ; v1(31.37,40.13) R185.2 C84.1 R189.1
  L3_SIG1 w0.254: v1(36.83,24.64) 36.83,24.65 34.27,27.2 29.16,27.2 23.39,32.97 23.39,36.5 24.21,37.31 27.76,37.31 30.58,40.13 v1(31.37,40.13) ; v1(128.78,61.72) 128.78,62.05 128.27,62.56 128.27,63.13 128.9,63.76 131.15,63.76 131.57,64.19 131.57,66.78 130.89,67.46 130.89,68.55 128.22,71.21 126.8,71.21 125.45,69.87 124.27,69.87 123.3,70.84 118.06,70.84 116.81,72.09 111.84,72.09 111.1,71.35 109.5,71.35 v2(108.84,72.01)
  L4_SIG2 w0.254: v1(36.83,24.64) 38.73,22.73 38.73,15.62 36.96,13.84 36.96,5.84 40.39,2.41 54.99,2.41 55.98,1.42 127.48,1.42 128.1,2.04 134.12,8.06 134.12,39.24 130.81,42.55 128.78,42.55 128.14,43.18 128.14,45.47 131.39,48.72 131.39,51.61 130.94,52.07 130.94,58.17 128.78,60.32 v1(128.78,61.72) ; v1(85.35,67.5) 85.35,67.43 85.98,66.8 86.49,66.8 87.33,65.96 87.33,63.27 87.99,62.61 87.99,59.62 88.48,59.13 88.48,58.45 88.09,58.06 88.09,54.97 88.72,54.34 89.56,53.5 89.56,50.83 91.16,49.22 92.38,49.22 93.12,48.49 93.12,48.08 v1(96.55,44.65)
  BOTTOM w0.254: v1(96.55,44.65) 96.55,46.66 97.28,47.4 97.28,51.18 v1(102.36,56.26) ; R436.2 v2(108.84,72.01)
IS_IHB3: length 110.8
  TOP w0.13: U11.AC13 86.99,67.16 v1(86.65,67.5)
  TOP w0.254: v1(102.87,69.93) 102.87,70.74 R103.2
  L3_SIG1 w0.13: 90,68.33 89.53,68.33 88.71,67.5 v1(86.65,67.5)
  L3_SIG1 w0.254: v1(99.06,27.82) 97.09,27.82 92.81,23.55 91.16,23.55 90.32,22.71 84.53,22.71 83.61,21.79 80.92,21.79 80.64,22.07 77.98,22.07 76.96,22.07 76.31,22.72 75.43,22.72 72.26,25.88 69.7,25.88 67.26,28.32 v1(64.52,28.32) ; 90,68.33 97.9,68.33 99.5,69.93 v1(102.87,69.93)
  L4_SIG2 w0.254: v1(99.06,27.82) 99.29,28.05 99.29,30.3 99.44,30.45 99.44,31.37 99.01,31.8 99.01,34.63 99.01,36.07 97.63,37.44 97.63,44.91 92.6,49.94 91.57,49.94 90.22,51.28 90.22,53.85 88.91,55.16 88.91,59.4 88.49,59.82 88.49,62.81 87.78,63.53 87.78,66.37 v1(86.65,67.5)
  BOTTOM w0.254: v1(64.52,28.32) 64.14,27.94 64.14,26.59 63.58,26.03 R523.1 C333.1 R539.2
IS_MIHB1: length 132.8
  TOP w0.13: v1(85.03,67.98) U11.Y15
  L3_SIG1 w0.254: v1(82.96,14.55) 84.43,13.08 89.67,13.08 90.81,11.94 91.95,11.94 92.62,11.27 94.55,11.27 95.19,11.92 96.52,11.92 97.84,13.24 97.84,14.94 98.37,15.47 98.7,15.47 99.92,16.69 v1(99.92,17.32)
  L4_SIG2 w0.13: 87.4,68.77 85.83,68.77 v1(85.03,67.98)
  L4_SIG2 w0.254: 87.4,68.77 87.82,68.77 88.8,67.79 88.8,63.96 90.2,62.56 90.2,61.21 90.63,60.78 91.14,60.78 92.71,59.2 92.71,55.73 92.94,55.5 92.94,54.29 92.75,54.09 92.75,53.12 93.52,52.34 93.52,51.93 94.94,50.5 96.67,50.5 96.84,50.34 96.84,50.31 98.97,48.17 98.97,39.24 100.33,37.89 100.33,34.08 100.33,32.49 101.1,31.71 101.1,27.85 100.43,27.17 100.43,22.23 99.54,21.35 99.54,18.87 99.92,18.49 v1(99.92,17.32)
  BOTTOM w0.254: v1(82.96,14.55) 82.04,15.47 77.32,15.47 74.55,18.24 70.51,18.24 68.38,20.37 59.49,20.37 58.22,21.64 58.22,25.3 58.83,25.91 58.83,29.74 59.59,30.51 59.59,34.84 58.93,35.5 58.93,37.46 59.94,38.48 C286.1 R497.1
IS_MIHB2: length 175
  TOP w0.203: U11.AB16 86.33,69.11 v1(86,69.45)
  TOP w0.254: R188.1 28.58,40.13 C83.1 25.25,40.13 23.7,38.58 23.7,31.57 24.66,30.61 26.44,30.61 27.64,29.41 v1(27.64,27.43)
  L3_SIG1 w0.254: v1(27.64,27.43) 28.52,26.54 33.05,26.54 39.4,20.19 39.4,18.19 41.88,15.7 44.23,15.7 45.51,14.42 51.8,14.42 54.81,11.41 54.81,10.77 57,8.59 60.98,8.59 62.59,10.19 63.89,10.19 65.28,11.58 65.28,12.54 69.02,16.28 75.73,16.28 75.83,16.18 76.65,16.18 78.03,14.8 78.03,14.26 78.03,14.26 78.03,13.51 78.71,12.83 82.75,12.83 83.72,11.86 88.38,11.86 88.96,11.28 91.68,11.28 92.35,10.61 94.82,10.61 95.47,11.26 96.86,11.26 99.29,13.69 99.82,13.69 100.76,14.63 v1(100.76,17.93)
  L4_SIG2 w0.13: 87.45,69.19 87.01,69.19 86.84,69.03 86.42,69.03 v1(86,69.45)
  L4_SIG2 w0.254: 87.45,69.19 88.34,69.19 89.27,68.26 89.27,64.42 91.27,62.42 91.27,61.59 93.37,59.48 93.37,56.39 96.32,53.44 96.32,53.27 97.5,52.09 97.5,50.58 99.63,48.45 99.63,39.51 100.99,38.16 100.99,33.81 100.99,32.76 101.76,31.99 101.76,27.57 101.09,26.9 101.09,20.19 100.76,19.86 v1(100.76,17.93)
IS_MIHB3: length 102.1
  TOP w0.254: U11.AB15 v1(86.33,67.98)
  L3_SIG1 w0.254: v1(70.05,22.45) 70.97,22.45 71.75,23.24 73.97,23.24 75.14,22.07 75.15,22.06 76.04,22.06 77.12,20.98 77.57,20.98 77.75,20.8 78.59,20.8 79.12,21.34 80.27,21.34 80.7,20.91 80.7,20.22 81.07,19.84 81.84,19.84 83.13,21.13 84.25,21.13 85.17,22.05 90.05,22.05 90.05,22.05 90.59,22.05 91.43,22.89 93.78,22.89 96.44,25.55 99.38,25.55 99.85,26.03 99.85,26.55 99.75,26.66 v1(99.75,26.97)
  L4_SIG2 w0.13: v1(86.33,67.98) 86.76,68.4 87.3,68.4 87.3,68.4
  L4_SIG2 w0.254: v1(99.75,26.97) 99.75,27.42 100.44,28.12 100.44,31.44 99.67,32.22 99.67,34.35 99.67,37.61 98.31,38.97 98.31,47.86 96.52,49.65 94.51,49.65 92.86,51.31 92.86,51.99 91.63,53.22 91.63,55.16 91.75,55.29 91.75,59.23 90.87,60.12 90.36,60.12 89,61.47 89,63.02 88.32,63.7 88.32,67.39 87.3,68.4
  BOTTOM w0.254: v1(70.05,22.45) 60.2,22.45 59.82,22.83 59.82,24.26 60.58,25.02 C334.1 62.48,25.02 R524.1
JTAG_EMU0: length 112
  TOP w0.13: U11.N23 80.43,73.65 80.13,73.35 v1(80.13,73.35) ; J7.13 134.62,82.04 v1(132.59,80.01)
  L3_SIG1 w0.13: v1(80.13,73.35) 80.21,73.43 80.21,76.59 81.25,77.63 81.25,80.7 82.04,81.48 82.04,82.47 81.66,82.85 81.66,84.96 82.42,85.72 82.42,87.5 84.96,90.04 89.54,90.04 90.68,91.19 96.61,91.19 107.41,101.98 112.61,101.98 113.63,103 119.25,103 119.84,102.41 120.7,102.41 121.93,103.63 123.7,103.63 132.46,94.87 132.46,92.71 133.2,91.97 133.2,87.86 v2(132.33,87) 132.96,86.37 132.96,80.38 v1(132.59,80.01)
  BOTTOM w0.13: R402.1 134.62,82.04 v1(132.59,80.01) ; R376.1 125.73,85.34 125.73,87.07 127.89,89.23 129.54,89.23 130.12,88.65 130.12,88.16 131.28,87 v2(132.33,87)
JTAG_EMU1: length 64.1
  TOP w0.13: v1(83.72,79.68) 83.72,78.69 82.51,77.48 82.51,75.54 82.13,75.15 82.13,74.61 U11.T24 ; v1(127.64,82.42) 128.02,82.04 J7.14
  L3_SIG1 w0.13: v1(127.64,82.42) 127.04,83.02 125.19,83.02 124.33,82.17 123.57,82.17 120.45,79.05 112.7,79.05 112.52,78.87 108,78.87 v1(107.75,79.12)
  BOTTOM w0.13: R403.1 129.03,82.04 128.65,82.42 v1(127.64,82.42) R381.1 ; v1(107.75,79.12) 107.52,79.12 107.51,79.12 107.31,79.12 106.26,80.18 106.26,81.83 105.92,82.17 104.32,82.17 103.88,82.6 98.02,82.6 96.21,80.79 95.07,80.79 94.11,81.75 86.11,81.75 85.33,80.97 85.33,80.74 84.27,79.68 v1(83.72,79.68)
JTAG_TCK: length 76
  TOP w0.13: U11.AA25 85.68,77.86 86.69,78.87 v1(86.69,81.25)
  L3_SIG1 w0.13: v1(126.75,75.69) 126.75,76.07 126.05,76.77 124.14,76.77 122.17,78.74 113.28,78.74 112.9,78.36 v1(108.64,78.36)
  BOTTOM w0.13: v1(126.75,75.69) 126.76,75.69 127.07,75.38 U45.13 127.07,71.3 127.56,70.82 127.56,70 128.22,69.34 129.08,69.34 129.94,70.19 130.82,70.19 134.08,73.45 134.08,75.47 132.97,76.58 132.97,78.36 134.11,79.5 R413.2 R407.2 ; v1(108.64,78.36) 107.8,78.36 107.34,78.82 105.59,78.82 104.8,79.6 104.8,80.62 103.12,82.3 98.16,82.3 96.35,80.48 94.75,80.48 93.98,81.25 v1(86.69,81.25)
JTAG_TDI: length 79.6
  TOP w0.13: v1(85.75,72.07) 85.39,71.7 85.37,71.7 U11.Y20 ; J7.3 v1(137.67,75.69)
  L3_SIG1 w0.13: v1(127,70.61) 127,70.1 126.11,69.22 124.08,69.22 123.05,70.24 113.04,70.24 112.39,69.6 112.39,66.8 110.49,64.9 109.09,64.9 107.44,63.25 106.17,63.25 102.94,60.01 102.48,60.01 97.53,55.07 96.66,55.07 v1(96.52,55.21)
  L4_SIG2 w0.13: v1(137.67,75.69) 136.97,74.99 134.84,74.99 130.46,70.61 v1(127,70.61) ; v1(85.75,72.07) 86.03,72.07 86.35,71.75 87.63,71.75 90.42,68.96 90.42,65.19 92.63,62.99 92.63,62.15 96.13,58.65 96.13,55.6 v1(96.52,55.21)
  BOTTOM w0.13: v1(127,70.61) 126.42,71.19 U45.12
JTAG_TDO: length 96.6
  TOP w0.13: v1(130.68,69.72) 133.1,72.14 133.1,77.47 133.86,78.23 J7.7 ; U11.AA24 85.37,74.62 85.37,77.87 86.19,78.69 v1(86.19,79.71)
  L3_SIG1 w0.13: v1(108.74,77.44) 110.26,77.44 111.35,76.35 119.86,76.35 121.14,75.07 125.8,75.07 126.09,74.78 127.05,74.78 129.22,72.61 129.22,71.19 v1(130.68,69.72)
  L4_SIG2 w0.13: v1(135.42,50.42) 134.17,51.67 134.17,52.18 135.26,53.26 135.26,67.82 134.18,68.9 131.51,68.9 v1(130.68,69.72)
  BOTTOM w0.13: v1(86.19,79.71) 86.58,80.1 93.22,80.1 93.76,79.56 96.81,79.56 98.56,81.3 102.06,81.3 103.63,79.73 103.63,78.63 105.27,76.99 108.28,76.99 v1(108.74,77.44) ; v1(135.42,50.42) 135.04,50.8 133.86,50.8 133.42,50.36 U49.2
